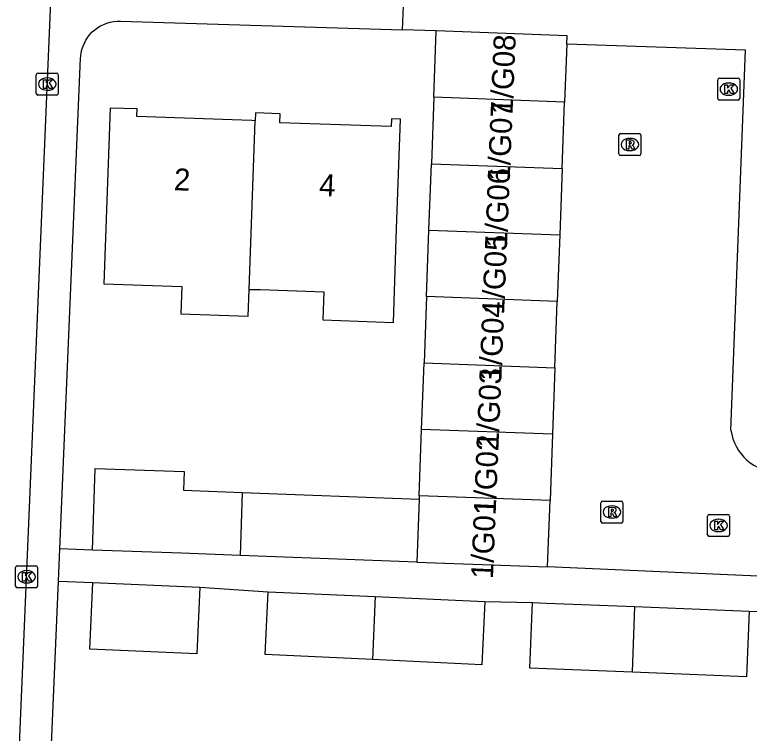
# Model space of a CAD drawing. Extents: x 161355 to 162026, y 386504 to 387459.
# Drawn here: x 161567.23 to 161600.69, y 387313.91 to 387346.64 of the extents above; entities that cross this region are included whole.
import ezdxf

# ---------------------------------------------------------------- set-up
doc = ezdxf.new("R2010")
doc.units = 0
for name, color, linetype in [('IMGEO_Kolk', 7, 'Continuous'), ('IMGEO_Pand', 7, 'Continuous'), ('IMGEO_Pand_nummerreeks', 7, 'Continuous'), ('IMGEO_Rijbaan_lokaal_open', 7, 'Continuous'), ('IMGEO_Rioolput', 7, 'Continuous'), ('IMGEO_Voetpad_open', 7, 'Continuous')]:
    doc.layers.add(name, color=color, linetype=linetype)

msp = doc.modelspace()

# ---------------------------------------------------------------- linework, layer by layer
at = {"layer": 'IMGEO_Kolk'}
for p, q in [((161568.285, 387343.982), (161569.137, 387343.982)), ((161568.21, 387343.056), (161568.21, 387343.908)), ((161568.698, 387343.762), (161568.723, 387343.762)), ((161569.211, 387343.908), (161569.211, 387343.056)), ((161599.253, 387342.825), (161599.253, 387343.677)), ((161599.328, 387343.751), (161600.18, 387343.751)), ((161600.254, 387343.677), (161600.254, 387342.825)), ((161599.741, 387343.531), (161599.766, 387343.531)), ((161569.137, 387342.982), (161568.285, 387342.982)), ((161568.721, 387343.202), (161568.696, 387343.202)), ((161600.18, 387342.751), (161599.328, 387342.751)), ((161599.764, 387342.971), (161599.739, 387342.971)), ((161598.789, 387322.956), (161598.789, 387323.808)), ((161598.864, 387323.882), (161599.716, 387323.882)), ((161599.277, 387323.662), (161599.302, 387323.662)), ((161599.79, 387323.808), (161599.79, 387322.956)), ((161599.3, 387323.102), (161599.275, 387323.102)), ((161599.716, 387322.882), (161598.864, 387322.882)), ((161567.266, 387320.617), (161567.266, 387321.469)), ((161567.341, 387321.543), (161568.193, 387321.543)), ((161567.754, 387321.323), (161567.779, 387321.323)), ((161568.267, 387321.469), (161568.267, 387320.617)), ((161567.777, 387320.763), (161567.752, 387320.763)), ((161568.193, 387320.543), (161567.341, 387320.543))]:
    msp.add_line(p, q, dxfattribs=at)
for points in [[(161568.285, 387343.982), (161569.137, 387343.982)], [(161568.21, 387343.056), (161568.21, 387343.908)], [(161568.531, 387343.682), (161568.654, 387343.682), (161568.654, 387343.531), (161568.784, 387343.682), (161568.948, 387343.682), (161568.802, 387343.531), (161568.955, 387343.282), (161568.803, 387343.282), (161568.718, 387343.446), (161568.654, 387343.379), (161568.654, 387343.282), (161568.531, 387343.282), (161568.531, 387343.682)], [(161569.211, 387343.908), (161569.211, 387343.056)], [(161599.253, 387342.825), (161599.253, 387343.677)], [(161599.328, 387343.751), (161600.18, 387343.751)], [(161600.254, 387343.677), (161600.254, 387342.825)], [(161599.574, 387343.451), (161599.697, 387343.451), (161599.697, 387343.3), (161599.827, 387343.451), (161599.991, 387343.451), (161599.845, 387343.3), (161599.998, 387343.051), (161599.846, 387343.051), (161599.761, 387343.215), (161599.697, 387343.148), (161599.697, 387343.051), (161599.574, 387343.051), (161599.574, 387343.451)], [(161569.137, 387342.982), (161568.285, 387342.982)], [(161600.18, 387342.751), (161599.328, 387342.751)], [(161598.789, 387322.956), (161598.789, 387323.808)], [(161598.864, 387323.882), (161599.716, 387323.882)], [(161599.11, 387323.582), (161599.233, 387323.582), (161599.233, 387323.431), (161599.363, 387323.582), (161599.527, 387323.582), (161599.381, 387323.431), (161599.534, 387323.182), (161599.382, 387323.182), (161599.297, 387323.346), (161599.233, 387323.279), (161599.233, 387323.182), (161599.11, 387323.182), (161599.11, 387323.582)], [(161599.79, 387323.808), (161599.79, 387322.956)], [(161599.716, 387322.882), (161598.864, 387322.882)], [(161567.266, 387320.617), (161567.266, 387321.469)], [(161567.341, 387321.543), (161568.193, 387321.543)], [(161567.587, 387321.243), (161567.71, 387321.243), (161567.71, 387321.092), (161567.84, 387321.243), (161568.004, 387321.243), (161567.858, 387321.092), (161568.011, 387320.843), (161567.859, 387320.843), (161567.774, 387321.007), (161567.71, 387320.94), (161567.71, 387320.843), (161567.587, 387320.843), (161567.587, 387321.243)], [(161568.267, 387321.469), (161568.267, 387320.617)], [(161568.193, 387320.543), (161567.341, 387320.543)]]:
    msp.add_lwpolyline(points, dxfattribs=at)
for centre, start, end in [((161568.287, 387343.906), 91.552, 178.448), ((161568.287, 387343.906), 91.552, 178.448), ((161569.135, 387343.906), 1.552, 88.448), ((161569.135, 387343.906), 1.552, 88.448), ((161599.33, 387343.675), 91.552, 178.448), ((161599.33, 387343.675), 91.552, 178.448), ((161600.178, 387343.675), 1.552, 88.448), ((161600.178, 387343.675), 1.552, 88.448), ((161568.287, 387343.058), 181.552, 268.448), ((161568.287, 387343.058), 181.552, 268.448), ((161569.135, 387343.058), 271.552, 358.448), ((161569.135, 387343.058), 271.552, 358.448), ((161599.33, 387342.827), 181.552, 268.448), ((161599.33, 387342.827), 181.552, 268.448), ((161600.178, 387342.827), 271.552, 358.448), ((161600.178, 387342.827), 271.552, 358.448), ((161598.866, 387323.806), 91.552, 178.448), ((161598.866, 387323.806), 91.552, 178.448), ((161599.714, 387323.806), 1.552, 88.448), ((161599.714, 387323.806), 1.552, 88.448), ((161598.866, 387322.958), 181.552, 268.448), ((161598.866, 387322.958), 181.552, 268.448), ((161599.714, 387322.958), 271.552, 358.448), ((161599.714, 387322.958), 271.552, 358.448), ((161567.343, 387321.467), 91.552, 178.448), ((161567.343, 387321.467), 91.552, 178.448), ((161568.191, 387321.467), 1.552, 88.448), ((161568.191, 387321.467), 1.552, 88.448), ((161567.343, 387320.619), 181.552, 268.448), ((161567.343, 387320.619), 181.552, 268.448), ((161568.191, 387320.619), 271.552, 358.448), ((161568.191, 387320.619), 271.552, 358.448)]:
    msp.add_arc(centre, 0.0765, start, end, dxfattribs=at)
for centre, major_axis, ratio, start_param, end_param in [((161568.697, 387343.482), (-0.387, 0.002), 0.722429, 4.712389, 7.853982), ((161568.722, 387343.482), (-0.39, 0.002), 0.717154, 1.570796, 4.712389), ((161599.74, 387343.251), (-0.387, 0.002), 0.722429, 4.712389, 7.853982), ((161599.765, 387343.251), (-0.39, 0.002), 0.717154, 1.570796, 4.712389), ((161599.276, 387323.382), (-0.387, 0.002), 0.722429, 4.712389, 7.853982), ((161599.301, 387323.382), (-0.39, 0.002), 0.717154, 1.570796, 4.712389), ((161567.753, 387321.043), (-0.387, 0.002), 0.722429, 4.712389, 7.853982), ((161567.778, 387321.043), (-0.39, 0.002), 0.717154, 1.570796, 4.712389)]:
    msp.add_ellipse(centre, major_axis=major_axis, ratio=ratio, start_param=start_param, end_param=end_param, dxfattribs=at)
at = {"layer": 'IMGEO_Pand'}
for points in [[(161586.316, 387342.879), (161586.427, 387345.903)], [(161592.371, 387345.293), (161592.385, 387345.685), (161586.427, 387345.903)], [(161592.371, 387345.293), (161592.274, 387342.66)], [(161586.316, 387342.879), (161586.206, 387339.854)], [(161592.274, 387342.66), (161586.316, 387342.879)], [(161592.164, 387339.636), (161592.274, 387342.66)], [(161578.175, 387341.813), (161578.027, 387341.818), (161577.134, 387341.85), (161572.788, 387342.003), (161572.8, 387342.347), (161571.575, 387342.39), (161571.293, 387334.385), (161574.835, 387334.26), (161574.792, 387333.021), (161577.859, 387332.913), (161577.902, 387334.129)], [(161577.902, 387334.129), (161578.074, 387334.126), (161578.074, 387334.134), (161578.428, 387334.122), (161581.304, 387334.02), (161581.259, 387332.743), (161584.474, 387332.63), (161584.624, 387336.887), (161584.8, 387341.883), (161584.391, 387341.898), (161584.378, 387341.543), (161579.305, 387341.722), (161579.319, 387342.126), (161578.188, 387342.166), (161578.175, 387341.813)], [(161577.902, 387334.129), (161578.175, 387341.813)], [(161586.095, 387336.83), (161586.206, 387339.854)], [(161586.206, 387339.854), (161592.164, 387339.636)], [(161592.164, 387339.636), (161592.053, 387336.612)], [(161585.984, 387333.805), (161586.095, 387336.83)], [(161586.095, 387336.83), (161592.053, 387336.612)], [(161592.053, 387336.612), (161591.942, 387333.587)], [(161585.984, 387333.805), (161585.873, 387330.781)], [(161591.942, 387333.587), (161585.984, 387333.805)], [(161591.831, 387330.562), (161591.942, 387333.587)], [(161585.762, 387327.756), (161585.873, 387330.781)], [(161585.873, 387330.781), (161591.831, 387330.562)], [(161591.831, 387330.562), (161591.72, 387327.538)], [(161585.652, 387324.732), (161585.762, 387327.756)], [(161591.72, 387327.538), (161585.762, 387327.756)], [(161591.72, 387327.538), (161591.61, 387324.514)], [(161570.762, 387322.251), (161570.887, 387325.981), (161574.941, 387325.845), (161574.912, 387324.982), (161577.588, 387324.881)], [(161577.588, 387324.881), (161577.492, 387322.012)], [(161577.588, 387324.881), (161585.646, 387324.575)], [(161585.646, 387324.575), (161585.537, 387321.707)], [(161585.652, 387324.732), (161585.646, 387324.575)], [(161591.61, 387324.514), (161585.652, 387324.732)], [(161591.499, 387321.489), (161591.61, 387324.514)], [(161577.492, 387322.012), (161574.816, 387322.114), (161570.762, 387322.251)], [(161585.537, 387321.707), (161577.492, 387322.012)], [(161585.537, 387321.707), (161591.499, 387321.489)], [(161575.652, 387320.575), (161575.522, 387317.535), (161570.65, 387317.743), (161570.779, 387320.783)], [(161570.779, 387320.783), (161575.652, 387320.575)], [(161583.53, 387317.273), (161578.638, 387317.504), (161578.769, 387320.365)], [(161578.769, 387320.365), (161583.64, 387320.143)], [(161583.64, 387320.143), (161583.53, 387317.273)], [(161588.639, 387319.915), (161588.507, 387317.038), (161583.53, 387317.273)], [(161583.64, 387320.143), (161588.639, 387319.915)], [(161595.361, 387316.697), (161590.689, 387316.883), (161590.808, 387319.868)], [(161590.808, 387319.868), (161591.446, 387319.843), (161595.48, 387319.682)], [(161595.361, 387316.697), (161595.48, 387319.682)], [(161595.48, 387319.682), (161600.682, 387319.474)], [(161600.682, 387319.474), (161600.563, 387316.49), (161595.361, 387316.697)]]:
    msp.add_lwpolyline(points, dxfattribs=at)
at = {"layer": 'IMGEO_Rijbaan_lokaal_open'}
for points in [[(161566.809, 387300.557), (161566.863, 387301.457), (161567.157, 387306.549), (161568.869, 387347.262), (161568.875, 387347.345), (161568.895, 387347.498), (161568.93, 387347.649), (161568.978, 387347.797), (161569.039, 387347.939), (161569.112, 387348.075), (161569.197, 387348.205), (161569.294, 387348.326), (161569.401, 387348.438), (161569.517, 387348.54), (161569.642, 387348.632), (161569.775, 387348.711), (161569.914, 387348.779), (161570.059, 387348.834), (161570.209, 387348.876), (161570.361, 387348.904), (161570.515, 387348.918), (161570.67, 387348.919), (161572.943, 387348.829)], [(161599.845, 387327.719), (161600.506, 387345.024), (161592.371, 387345.293)], [(161621.97, 387319.829), (161621.972, 387320.147), (161591.499, 387321.489)]]:
    msp.add_lwpolyline(points, dxfattribs=at)
msp.add_arc((161602.067, 387328.036), 2.244, 188.1195, 268.8001, dxfattribs=at)
at = {"layer": 'IMGEO_Rioolput'}
for p, q in [((161594.746, 387340.303), (161594.746, 387341.155)), ((161594.821, 387341.229), (161595.673, 387341.229)), ((161595.234, 387341.009), (161595.259, 387341.009)), ((161595.747, 387341.155), (161595.747, 387340.303)), ((161595.257, 387340.449), (161595.232, 387340.449)), ((161595.673, 387340.229), (161594.821, 387340.229)), ((161593.929, 387323.566), (161593.929, 387324.418)), ((161594.004, 387324.492), (161594.856, 387324.492)), ((161594.417, 387324.272), (161594.442, 387324.272)), ((161594.93, 387324.418), (161594.93, 387323.566)), ((161594.44, 387323.712), (161594.415, 387323.712)), ((161594.856, 387323.492), (161594.004, 387323.492))]:
    msp.add_line(p, q, dxfattribs=at)
for points in [[(161594.746, 387340.303), (161594.746, 387341.155)], [(161594.821, 387341.229), (161595.673, 387341.229)], [(161595.747, 387341.155), (161595.747, 387340.303)], [(161595.335, 387340.927), (161595.083, 387340.929), (161595.083, 387340.529)], [(161595.083, 387340.529), (161595.207, 387340.529), (161595.207, 387340.691), (161595.218, 387340.691)], [(161595.261, 387340.848), (161595.207, 387340.848), (161595.207, 387340.767)], [(161595.207, 387340.767), (161595.259, 387340.767)], [(161595.265, 387340.662), (161595.336, 387340.529), (161595.476, 387340.529), (161595.411, 387340.655)], [(161595.673, 387340.229), (161594.821, 387340.229)], [(161593.929, 387323.566), (161593.929, 387324.418)], [(161594.004, 387324.492), (161594.856, 387324.492)], [(161594.93, 387324.418), (161594.93, 387323.566)], [(161594.518, 387324.19), (161594.266, 387324.192), (161594.266, 387323.792)], [(161594.266, 387323.792), (161594.39, 387323.792), (161594.39, 387323.954), (161594.401, 387323.954)], [(161594.444, 387324.111), (161594.39, 387324.111), (161594.39, 387324.03)], [(161594.39, 387324.03), (161594.442, 387324.03)], [(161594.448, 387323.925), (161594.519, 387323.792), (161594.659, 387323.792), (161594.594, 387323.918)], [(161594.856, 387323.492), (161594.004, 387323.492)]]:
    msp.add_lwpolyline(points, dxfattribs=at)
for centre, radius, start, end in [((161594.823, 387341.153), 0.0765, 91.552, 178.448), ((161594.823, 387341.153), 0.0765, 91.552, 178.448), ((161595.671, 387341.153), 0.0765, 1.552, 88.448), ((161595.671, 387341.153), 0.0765, 1.552, 88.448), ((161595.217, 387340.638), 0.0533, 26.0293, 88.6989), ((161595.243, 387340.956), 0.19, 274.7715, 282.9687), ((161595.267, 387340.752), 0.0964, 77.0061, 93.1865), ((161595.281, 387340.809), 0.0378, 276.6634, 79.6772), ((161595.334, 387340.817), 0.109, 350.3612, 89.416), ((161595.332, 387340.817), 0.112, 277.5842, 350.9817), ((161595.316, 387340.602), 0.108, 29.5134, 73.7905), ((161594.823, 387340.305), 0.0765, 181.552, 268.448), ((161594.823, 387340.305), 0.0765, 181.552, 268.448), ((161595.671, 387340.305), 0.0765, 271.552, 358.448), ((161595.671, 387340.305), 0.0765, 271.552, 358.448), ((161594.006, 387324.416), 0.0765, 91.552, 178.448), ((161594.006, 387324.416), 0.0765, 91.552, 178.448), ((161594.854, 387324.416), 0.0765, 1.552, 88.448), ((161594.854, 387324.416), 0.0765, 1.552, 88.448), ((161594.4, 387323.901), 0.0533, 26.0293, 88.6989), ((161594.426, 387324.219), 0.19, 274.7715, 282.9687), ((161594.45, 387324.015), 0.0964, 77.0061, 93.1865), ((161594.464, 387324.072), 0.0378, 276.6634, 79.6772), ((161594.517, 387324.08), 0.109, 350.3612, 89.416), ((161594.515, 387324.08), 0.112, 277.5842, 350.9817), ((161594.499, 387323.865), 0.108, 29.5134, 73.7905), ((161594.006, 387323.568), 0.0765, 181.552, 268.448), ((161594.006, 387323.568), 0.0765, 181.552, 268.448), ((161594.854, 387323.568), 0.0765, 271.552, 358.448), ((161594.854, 387323.568), 0.0765, 271.552, 358.448)]:
    msp.add_arc(centre, radius, start, end, dxfattribs=at)
for centre, major_axis, ratio, start_param, end_param in [((161595.233, 387340.729), (-0.387, 0.002), 0.722429, 4.712389, 7.853982), ((161595.258, 387340.729), (-0.39, 0.002), 0.717154, 1.570796, 4.712389), ((161594.416, 387323.992), (-0.387, 0.002), 0.722429, 4.712389, 7.853982), ((161594.441, 387323.992), (-0.39, 0.002), 0.717154, 1.570796, 4.712389)]:
    msp.add_ellipse(centre, major_axis=major_axis, ratio=ratio, start_param=start_param, end_param=end_param, dxfattribs=at)
at = {"layer": 'IMGEO_Voetpad_open'}
for points in [[(161584.886, 387345.951), (161584.995, 387348.522)], [(161569.279, 387322.31), (161570.23, 387344.668), (161570.235, 387344.746), (161570.255, 387344.901), (161570.289, 387345.054), (161570.337, 387345.203), (161570.398, 387345.348), (161570.471, 387345.486), (161570.557, 387345.618), (161570.654, 387345.741), (161570.761, 387345.855), (161570.879, 387345.959), (161571.005, 387346.052), (161571.139, 387346.133), (161571.279, 387346.202), (161571.426, 387346.259), (161571.576, 387346.302), (161571.73, 387346.331), (161571.886, 387346.347), (161572.043, 387346.348), (161584.886, 387345.951)], [(161586.427, 387345.903), (161584.886, 387345.951)], [(161569.217, 387320.842), (161569.279, 387322.31)], [(161570.762, 387322.251), (161569.279, 387322.31)], [(161569.658, 387297.867), (161569.525, 387297.884), (161569.395, 387297.914), (161569.269, 387297.954), (161569.146, 387298.006), (161569.028, 387298.069), (161568.917, 387298.142), (161568.812, 387298.225), (161568.716, 387298.316), (161568.628, 387298.416), (161568.549, 387298.524), (161568.48, 387298.638), (161568.421, 387298.758), (161568.374, 387298.882), (161568.337, 387299.01), (161568.313, 387299.141), (161568.3, 387299.274), (161569.217, 387320.842)], [(161569.217, 387320.842), (161570.779, 387320.783)], [(161575.652, 387320.575), (161578.769, 387320.365)], [(161588.639, 387319.915), (161590.808, 387319.868)], [(161600.682, 387319.474), (161603.153, 387319.416)]]:
    msp.add_lwpolyline(points, dxfattribs=at)

# ---------------------------------------------------------------- texts
at = {"layer": 'IMGEO_Pand_nummerreeks'}
for s, rotation, p in [('1/G08', 87.5881, (161589.899, 387342.078)), ('1/G07', 87.5853, (161589.771, 387339.038)), ('2', 357.7597, (161574.464, 387338.649)), ('4', 357.7597, (161581.078, 387338.39)), ('1/G06', 87.5853, (161589.643, 387336.002)), ('1/G05', 87.5853, (161589.515, 387332.966)), ('1/G04', 87.5853, (161589.387, 387329.93)), ('1/G03', 87.5853, (161589.259, 387326.894)), ('1/G02', 87.5853, (161589.131, 387323.851)), ('1/G01', 87.5853, (161589.008, 387320.932))]:
    msp.add_text(s, height=1, rotation=rotation, dxfattribs=at).set_placement(p)

doc.saveas('drawing.dxf')
